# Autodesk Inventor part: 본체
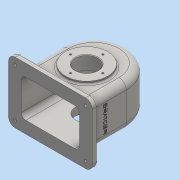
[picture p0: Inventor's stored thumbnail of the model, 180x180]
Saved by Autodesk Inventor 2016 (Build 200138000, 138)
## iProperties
Created: 2018-11
Part Number: 본체
Material: 일반
Document SubType Name: Modeling
Designer: 공506_40
Density: 1 g/cm^3
Appearance: 기본값
Mass: 404.434 g
Surface Area: 1182.57 cm^2
Volume: 404.434 cm^3
Author: 공506_40
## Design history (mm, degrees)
sketch "스케치3"
  geometry: L1 (-75, 55)-(75, 55); L2 (75, 55)-(75, -55); L3 (75, -55)-(-75, -55); L4 (-75, -55)-(-75, 55); L5 (-75, 55)-(75, -55); L6 (75, 55)-(-75, -55); 1 further point
  constraints: 12 end point, 2 midpoint, 2 parallel, 1 horizontal, 1 perpendicular
  dimensions: "d4" = 150 distance of L2.end L3.end; "d5" = 110 distance of L3.end L1.start
extrude "돌출1" new body sketch "스케치3" distance "d6" = 10; taper "d7" = 0 deg
sketch "스케치4"
  geometry: L1 (58, -38.5)-(-58, -38.5); L2 (-58, -38.5)-(-58, 38.5); L3 (-58, 38.5)-(58, 38.5); L4 (58, 38.5)-(58, -38.5); L5 (58, -38.5)-(-58, 38.5); L6 (-58, -38.5)-(58, 38.5); 1 further point
  constraints: 12 end point, 2 midpoint, 2 parallel, 1 horizontal, 1 perpendicular
  dimensions: "d8" = 77 distance of L1.end L2.end; "d9" = 116 distance of L2.end L3.end
extrude "돌출2" join sketch "스케치4" distance "d10" = 126; taper "d11" = 0 deg
fillet "모깎기1" dims "d12" = 58
fillet "모깎기2" dims "d13" = 12
fillet "모깎기3" dims "d14" = 3
sketch "스케치5"
  geometry: L1 (-75, -43)-(-75, 43) reference; L2 (-63, 55)-(63, 55) reference; L3 (75, 43)-(75, -43) reference; L4 (63, -55)-(-63, -55) reference; A1 r 12 centre (-63, -43) between (-75, -43) and (-63, -55) reference; A2 r 12 centre (-63, 43) between (-63, 55) and (-75, 43) reference; A3 r 12 centre (63, 43) between (75, 43) and (63, 55) reference; A4 r 12 centre (63, -43) between (63, -55) and (75, -43) reference; 5 further points
  constraints: 4 coincident
hole "구멍1" sketch "스케치5" at (-63, -43), (-63, 43), (63, 43), (63, -43) diameter "d15" = 5; stored, may be unused: countersink angle "d19" = 90 deg, drill point angle "d21" = 118 deg; dims "d16" = 6, "d17" = 12, "d18" = 4, "d20" = 10
sketch "스케치9"
  geometry: L1 (58, 0)-(58, 68) reference; L2 (-58, 0)-(-58, 68) reference; L3 (63, -10)-(-63, -10) reference; L4 (-52, -10)-(-52, 68); L5 (52, 68)-(52, -10); L6 (52, -10)-(-52, -10); A1 r 58 centre (0, 68) between (58, 68) and (-58, 68) reference; A2 r 52 centre (0, 68) between (52, 68) and (-52, 68); 1 further point
  constraints: 6 end point, 2 point on circle, 2 point on line, 2 tangent, 2 vertical, 1 centre point, 1 collinear
  dimensions: "d27" = 6 radial gap between concentric circles of A1 A2
extrude "돌출3" cut sketch "스케치9" stored distance "d28" = 67; taper "d29" = 0 deg
sketch "스케치10"
  geometry: L1 (0, 0)-(0, 68) reference; C1 r 38 at (58, 55); 1 further point
  constraints: 1 centre point
  dimensions: "d30" = 55 distance of point (58, 0) C1.centre; "d31" = 58 distance from line of L1 C1.centre; "d32" = 76 diameter of C1
extrude "돌출4" join sketch "스케치10" distance "d33" = 5; taper "d34" = 0 deg
node "작업 평면1"
sketch "스케치12"
  geometry: C1 r 38 at (0, 55) reference; C2 r 28 at (0, 55); 1 further point
  constraints: 1 centre point, 1 coincident
  dimensions: "d36" = 56 diameter of C2
extrude "돌출5" join sketch "스케치12" stored distance "d37" = 5; taper "d38" = 40 deg
sketch "스케치13"
  geometry: L1 (0, 0)-(0, 68) reference; L2 (121, 0)-(-5, 0) reference; C1 r 38 at (58, 55); 1 further point
  constraints: 1 centre point
  dimensions: "d39" = 76 diameter of C1; "d40" = 58 distance from line of L1 C1.centre; "d41" = 55 distance from line of L2 C1.centre
extrude "돌출6" join sketch "스케치13" distance "d42" = 10; taper "d43" = 0 deg
sketch "스케치14"
  geometry: C1 r 38 at (0, 0) reference; C2 r 20 at (0, 0); 1 further point
  constraints: 1 centre point, 1 coincident
  dimensions: "d44" = 40 diameter of C2
extrude "돌출7" cut sketch "스케치14" distance "d45" = 247.25; taper "d46" = 0 deg
fillet "모깎기4" dims "d47" = 8
fillet "모깎기5" dims "d48" = 13
fillet "모깎기6" dims "d49" = 3
fillet "모깎기7" dims "d50" = 3
node "작업 평면2"
sketch "스케치15"
  geometry: C1 r 6 at (0, 0); 1 further point
  constraints: 1 centre point, 1 coincident
  dimensions: "d52" = 12 diameter of C1
extrude "돌출8" join sketch "스케치15" stored distance "d53" = 247.25; taper "d54" = 5 deg
fillet "모깎기8" dims "d55" = 3
sketch "스케치16"
  geometry: C1 r 20 at (0, 0) reference; 2 further points
  constraints: 1 vertical alignment
  dimensions: "d56" = 29 distance of C1.centre point (0, 29)
hole "구멍2" sketch "스케치16" at (0, 29) diameter "d57" = 3.242; stored, may be unused: countersink angle "d61" = 90 deg, drill point angle "d63" = 118 deg; dims "d58" = 8, "d59" = 12, "d60" = 4, "d62" = 10
sketch "스케치17"
  geometry: C1 r 20 at (0, 0) reference; 2 further points
  constraints: 1 horizontal alignment
  dimensions: "d67" = 29 distance of C1.centre point (29, 0)
hole "구멍3" sketch "스케치17" at (29, 0) diameter "d68" = 3.242; stored, may be unused: countersink angle "d72" = 90 deg, drill point angle "d74" = 118 deg; dims "d69" = 8, "d70" = 12, "d71" = 4, "d73" = 10
sketch "스케치18"
  geometry: 2 further points
  constraints: 1 coincident
hole "구멍4" sketch "스케치18" at (0, 0) diameter "d78" = 4.134; stored, may be unused: countersink angle "d82" = 90 deg, drill point angle "d84" = 118 deg; dims "d79" = 20, "d80" = 12, "d81" = 4, "d83" = 20
chamfer "모따기1" distance "d85" = 1; stored, may be unused: second distance "d86" = 2, angle "d87" = 45 deg
chamfer "모따기2" distance "d88" = 1; stored, may be unused: second distance "d89" = 2, angle "d90" = 45 deg
sketch "스케치19"
  geometry: L1 (68.5, -78)-(-17.5, -78) reference; L2 (-13, 0)-(-13, -65) reference; 2 further points
  constraints: 1 other
  dimensions: "d91" = 40 distance from line of L1 point (25.5, -38); "d92" = 38.5 distance from line of point (25.5, -38) L2
feature "엠보싱1" sketch "스케치19" dims "d4" = 150, "d5" = 110, "d93" = 0.5, "d94" = 0
node "솔리드1"
pattern_circular "원형 패턴1" dims angle "d65" = 360 deg
pattern_circular "원형 패턴2" dims angle "d76" = 360 deg
node "투영된 루프1"
node "투영된 루프3"
node "투영된 루프4"
other parameters: "d35" = 14, "d51" = 132
